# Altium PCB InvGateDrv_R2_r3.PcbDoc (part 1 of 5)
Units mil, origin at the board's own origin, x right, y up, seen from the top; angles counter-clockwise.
Board outline 6245 x 2850 mil, 4 copper layers (Top Layer, Power, Ground, Bottom Layer), stack 104.204 mil thick; 409 components, 181 nets, 1050 pads, 683 vias.
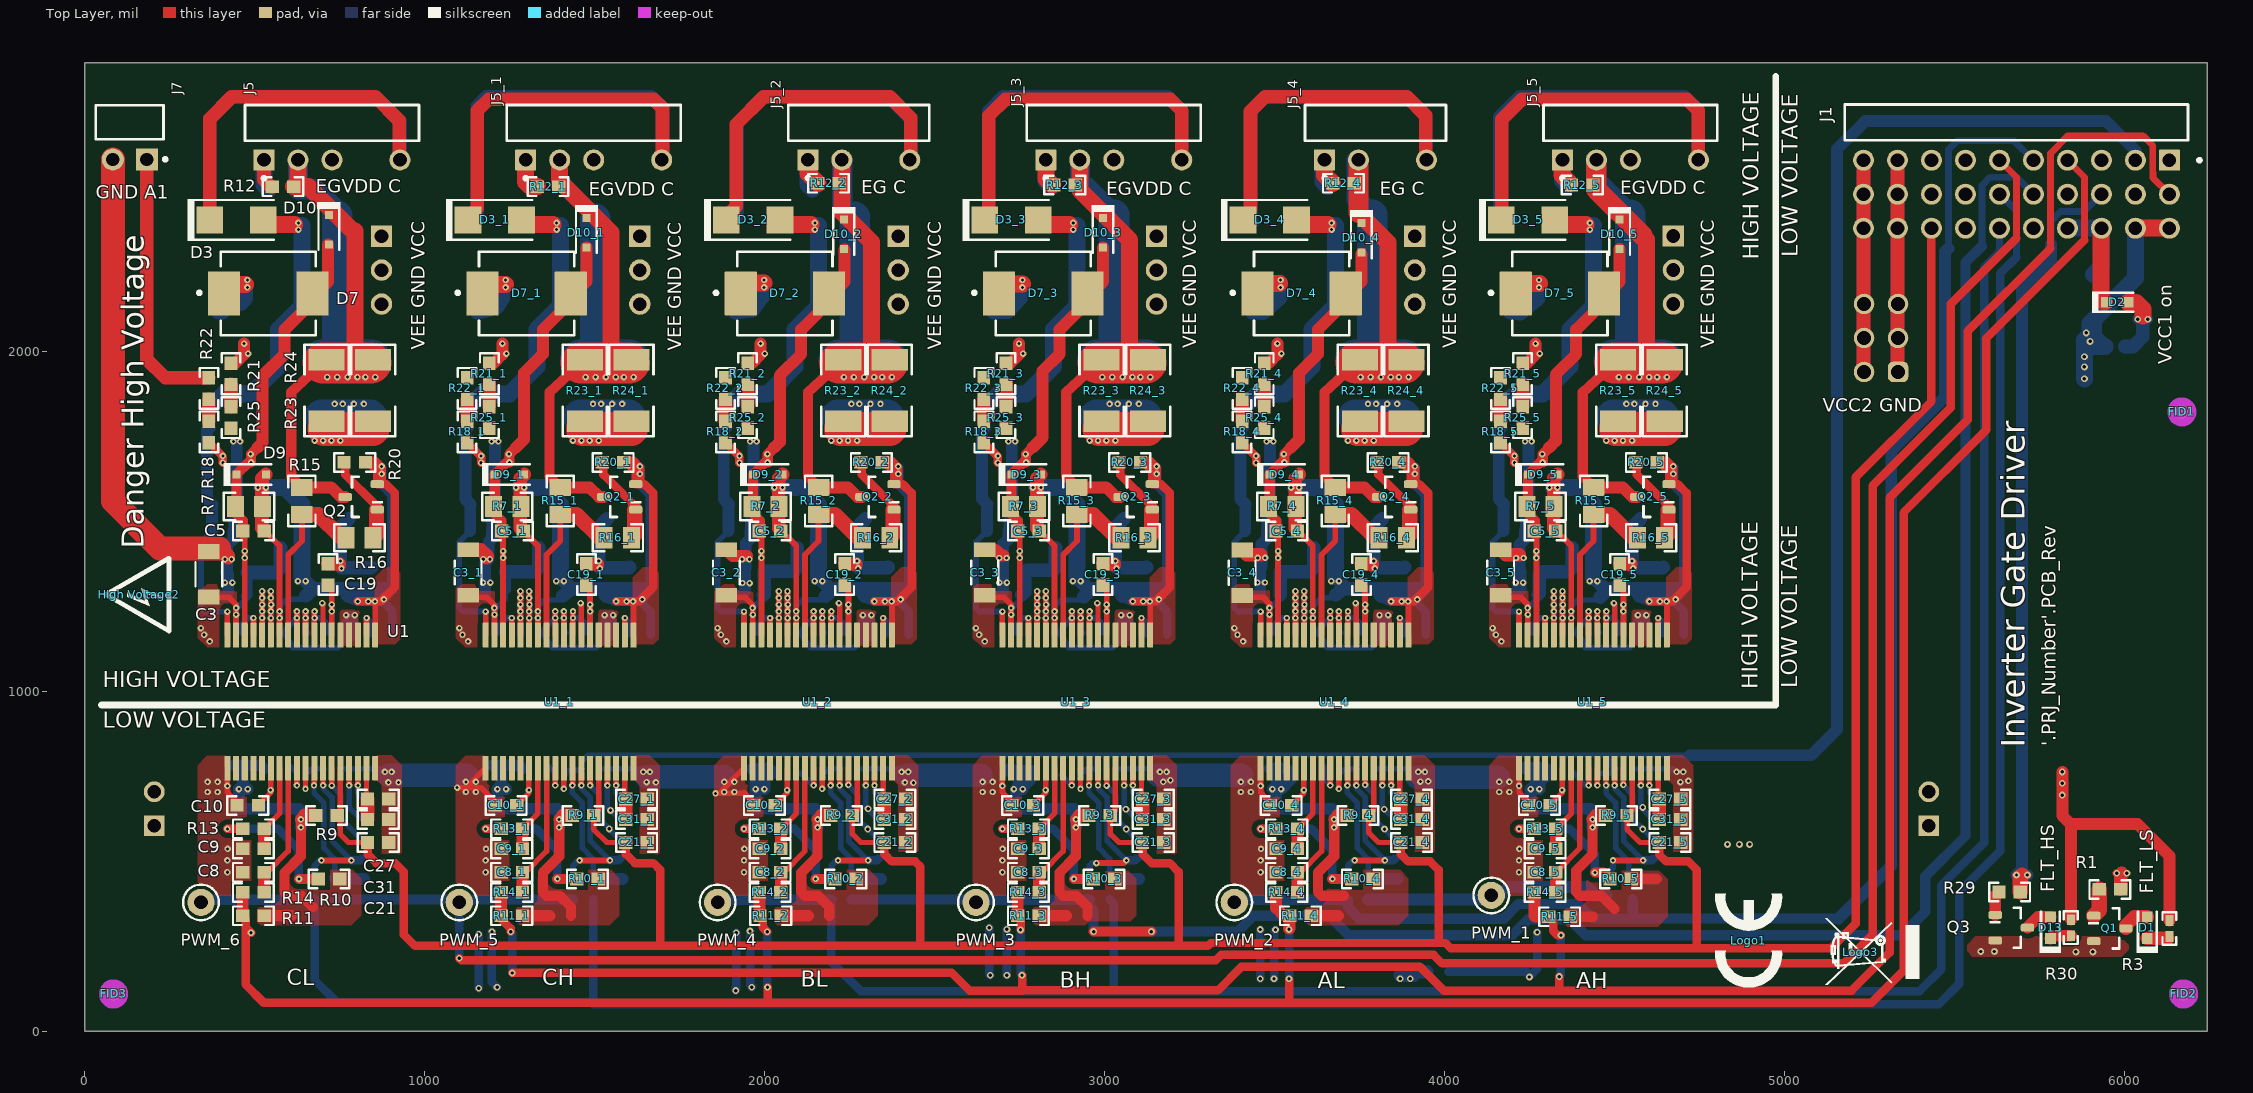
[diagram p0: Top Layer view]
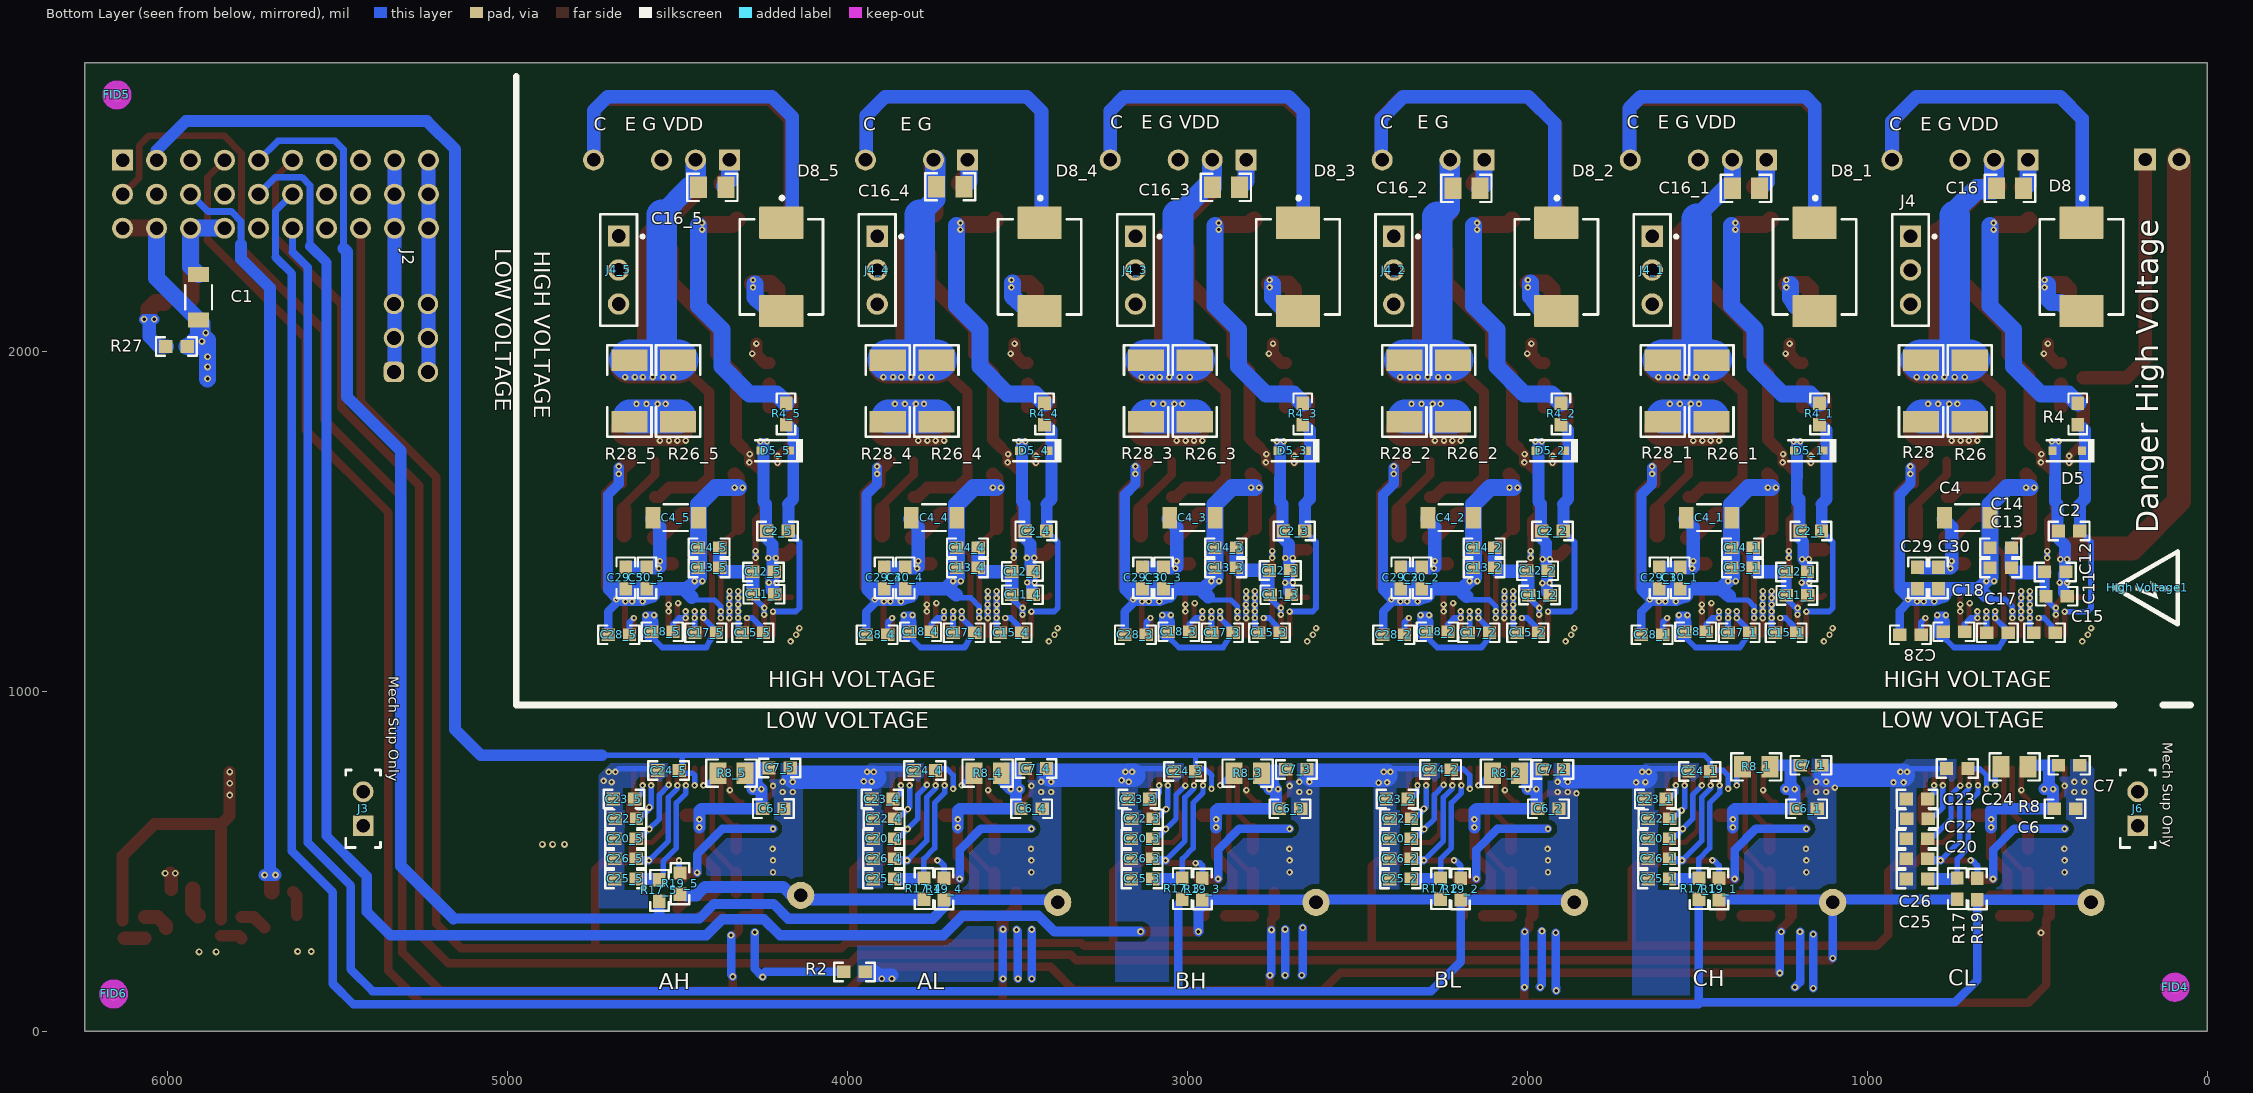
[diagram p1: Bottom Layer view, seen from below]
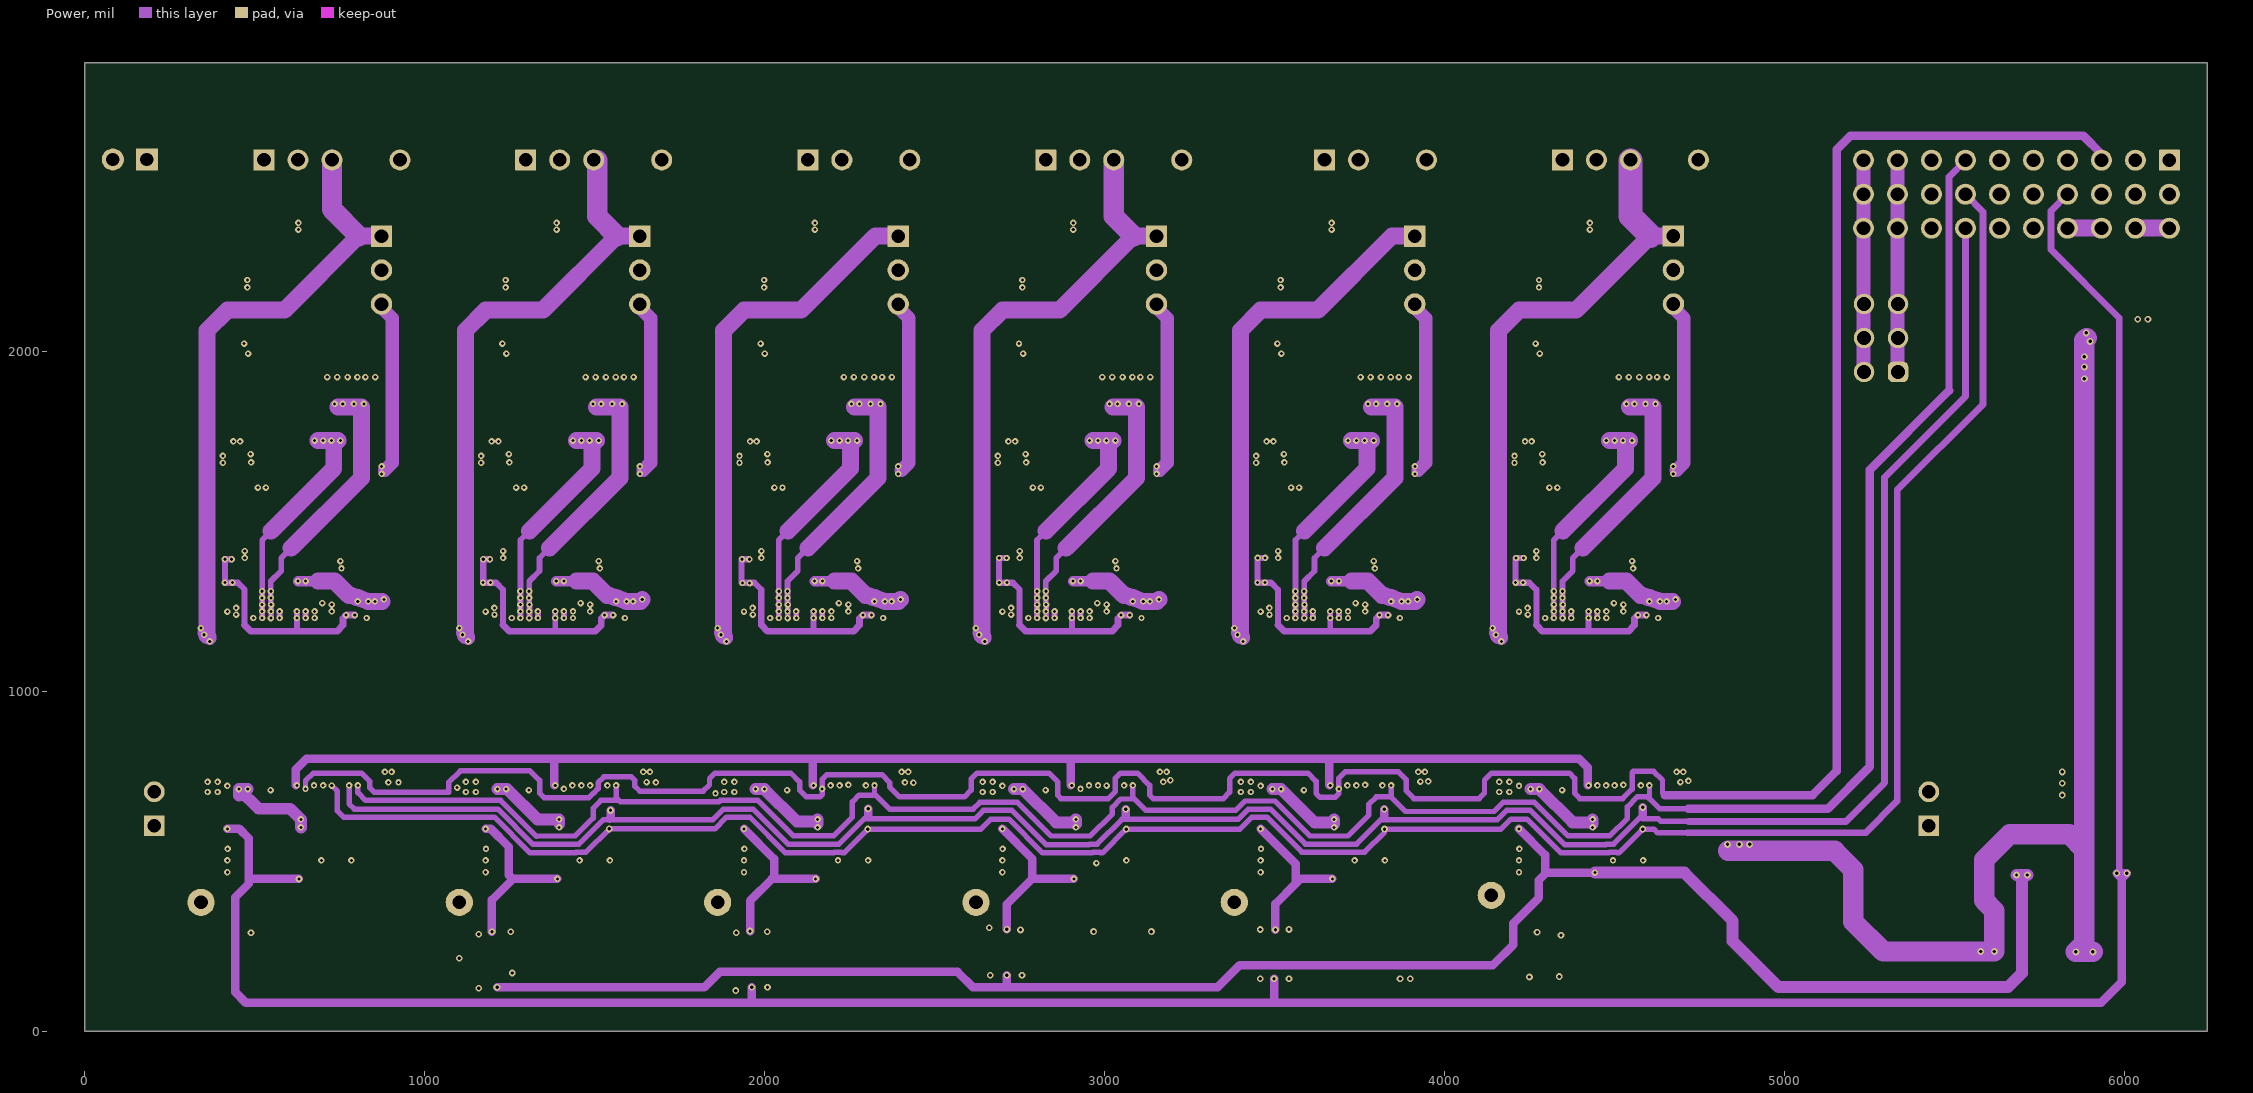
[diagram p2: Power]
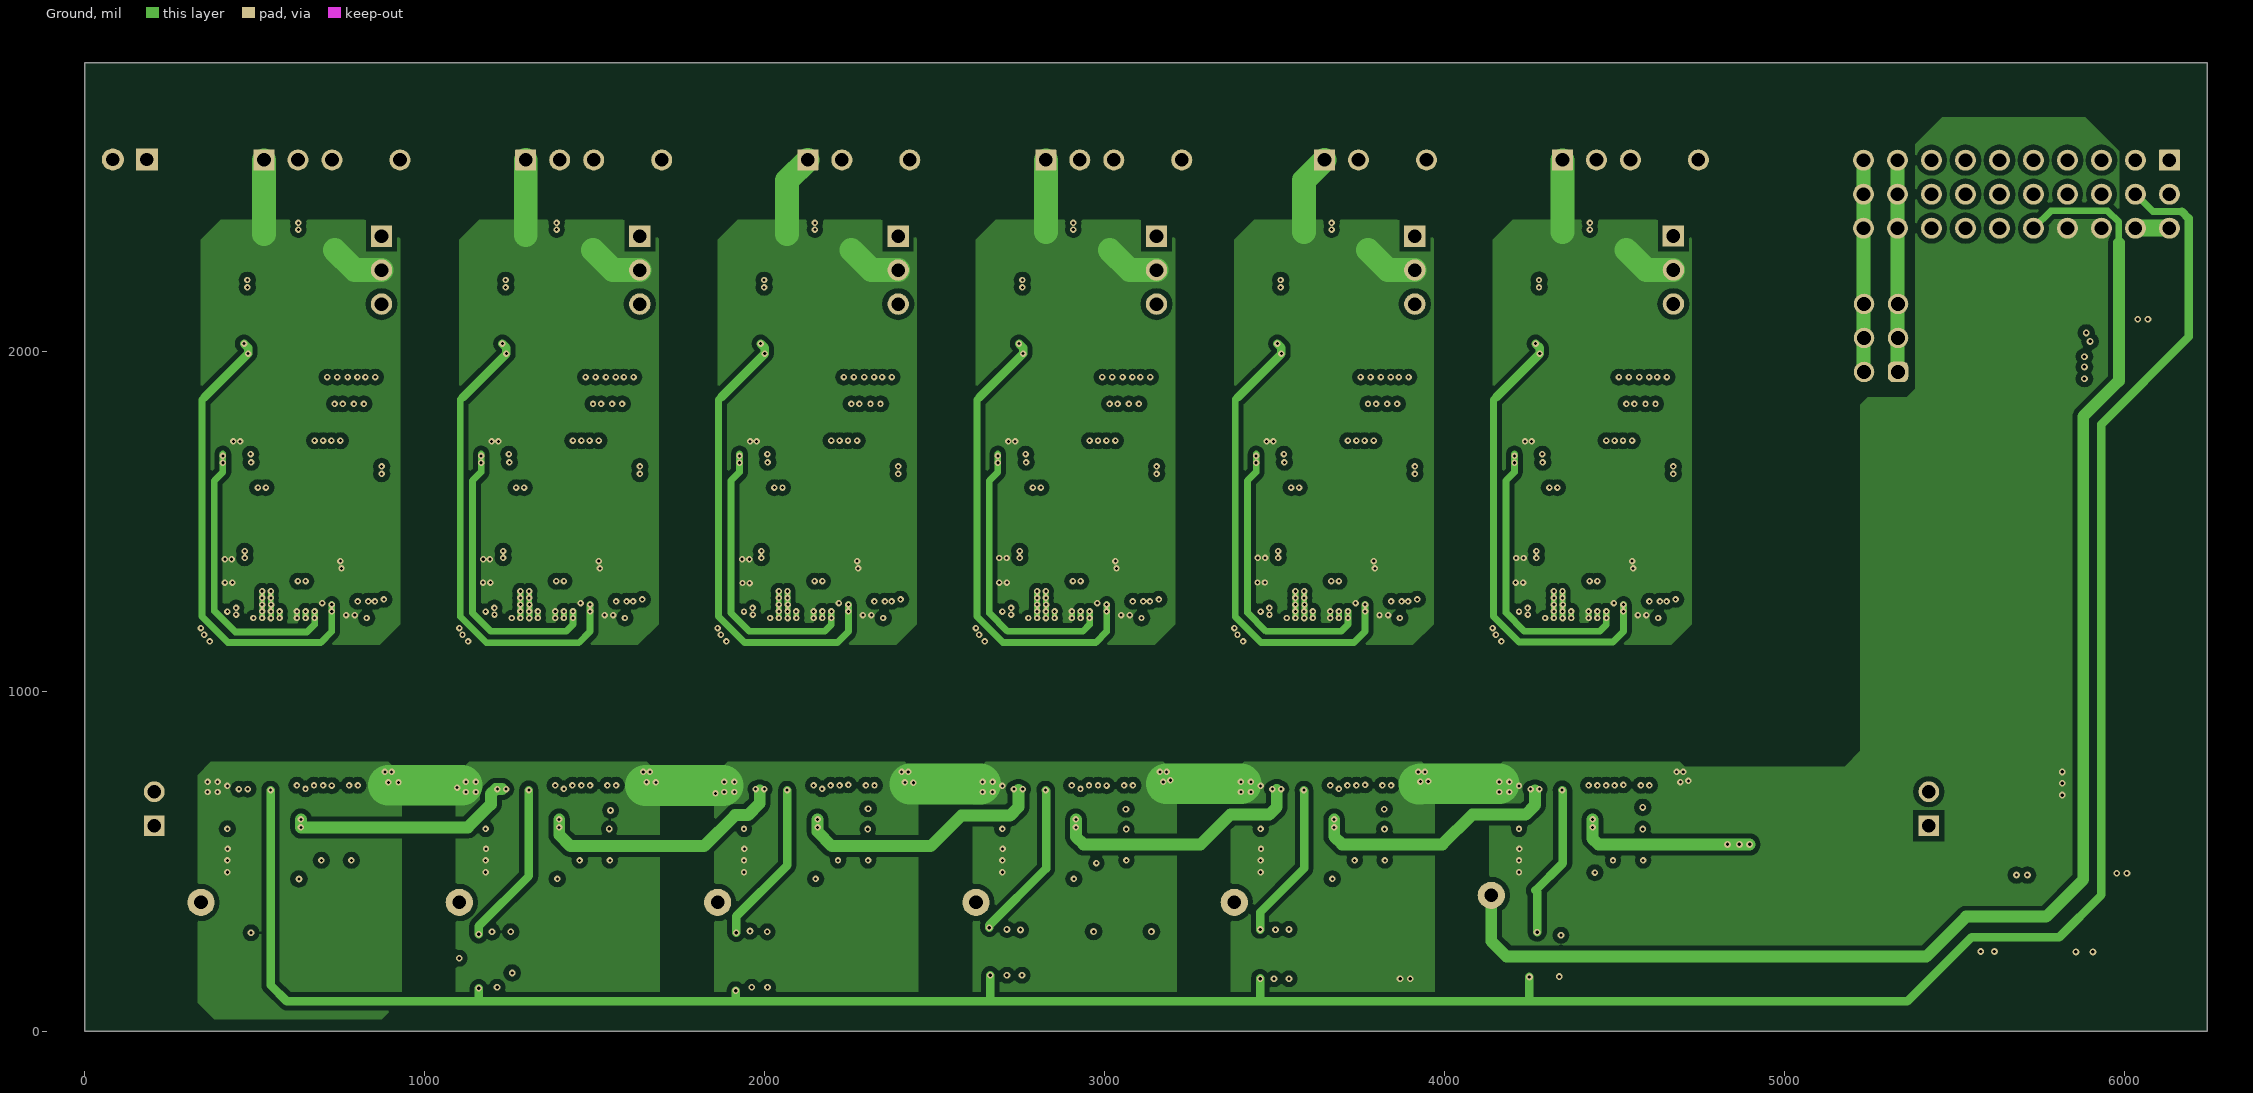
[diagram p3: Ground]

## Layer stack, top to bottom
Top Solder: solder mask 0.4, Solder Resist, Dk 3.5
Top Layer: signal copper 1.4
Dielectric 2: prepreg 19.685, FR-4, Dk 4.2
Power: signal copper 1.417
Dielectric1: core 59.2, FR-4, Dk 4.8
Ground: signal copper 1.417
Dielectric 3: prepreg 19.685, FR-4, Dk 4.2
Bottom Layer: signal copper 1.4
Bottom Solder: solder mask 0.4, Solder Resist, Dk 3.5

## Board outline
0,0 0,2850 6245,2850 6245,0

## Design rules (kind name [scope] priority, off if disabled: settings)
AcuteAngle [All] p1: minimum=4.50000000000000E+0001 checktracksonly=FALSE
AssemblyTestPointUsage [All] p1: valid=2
BoardOutlineClearance BoardOutlineClearance_MountingHoles [OnCopper and InComponentClass('Mounting Holes')] p1: gap=35 ignorepadtopadclearanceinfootprint=FALSE
BoardOutlineClearance BoardOutlineClearance_Poly [OnCopper and IsPoly] p2: gap=25 ignorepadtopadclearanceinfootprint=FALSE
BoardOutlineClearance [OnCopper and Not InComponentClass('Logo') and not InComponentClass('FiducialMark') and not InRegion(1000,500,4000,800) and not InPoly] p3: gap=25 ignorepadtopadclearanceinfootprint=FALSE
Clearance Clearance_Keepouts [((IsTrack Or IsArc) And Not InPoly) And IsFree and IsKeepOut vs ((IsTrack Or IsArc) And Not InPoly) And IsFree and IsKeepOut] p1: gap=0 ignorepadtopadclearanceinfootprint=FALSE
Clearance Clearance_Poly [InPolygon] p2: gap=15 ignorepadtopadclearanceinfootprint=TRUE
Clearance Clearance_FiducialMark [IsKeepOut and InComponentClass('FiducialMark') vs IsPad and InComponentClass('FiducialMark')] p3: gap=0 ignorepadtopadclearanceinfootprint=FALSE
Clearance [All] p4: gap=6 ignorepadtopadclearanceinfootprint=TRUE
ComponentClearance ComponentClearance_MountingHoles_FiducialMarks [InComponentClass('Mounting Holes') vs InComponentClass('FiducialMark')] p1: gap=50 collisioncheckmode=3 verticalgap=10 showdistances=FALSE
ComponentClearance ComponentClearance_Shunt [InComponentClass('Header') vs InComponentClass('Shunt')] p2: gap=0 collisioncheckmode=3 verticalgap=0 showdistances=FALSE
ComponentClearance ComponentClearance_Logo [InComponentClass('Logo')] p3: gap=50 collisioncheckmode=3 verticalgap=10 showdistances=FALSE
ComponentClearance ComponentClearance_ScrewToNut [(HasFootprint('NY PMS 440 0025 PH')) vs (HasFootprint('Keystone_1902C'))] p4: gap=5 collisioncheckmode=3 verticalgap=10 showdistances=FALSE
ComponentClearance ComponentClearance_MountingHoles [InComponentClass('Mounting Holes')] p5: gap=250 collisioncheckmode=3 verticalgap=100000 showdistances=FALSE
ComponentClearance ComponentClearance_SmallPassives [HasFootprint('0201*') or HasFootprint('0402*') or HasFootprint('0508') or HasFootprint('0603*') or HasFootprint('0612') or HasFootprint('0805*') or HasFootprint('0815*') or HasFootprint('0830*') or HasFootprint('1206*') or HasFootprint('1210*') or HasFootprint('1808*') or HasFootprint('1812*') or HasFootprint('1825*') or HasFootprint('2010*') or HasFootprint('2220*') or HasFootprint('2225*') or HasFootprint('2512*') or HasFootprint('2728*') or HasFootprint('3518*') vs HasFootprint('0201*') or HasFootprint('0402*') or HasFootprint('0508') or HasFootprint('0603*') or HasFootprint('0612') or HasFootprint('0805*') or HasFootprint('0815*') or HasFootprint('0830*') or HasFootprint('1206*') or HasFootprint('1210*') or HasFootprint('1808*') or HasFootprint('1812*') or HasFootprint('1825*') or HasFootprint('2010*') or HasFootprint('2220*') or HasFootprint('2225*') or HasFootprint('2512*') or HasFootprint('2728*') or HasFootprint('3518*')] p6: gap=14.96 collisioncheckmode=3 verticalgap=10 showdistances=FALSE
ComponentClearance ComponentClearance_THtoSMT [IsThruComponent vs IsSMTComponent] p7: gap=15 collisioncheckmode=3 verticalgap=15 showdistances=FALSE
ComponentClearance ComponentClearance_THtoTH [IsThruComponent vs IsThruComponent] p8: gap=20 collisioncheckmode=3 verticalgap=30 showdistances=FALSE
ComponentClearance [All] p9: gap=15 collisioncheckmode=3 verticalgap=10 showdistances=FALSE
DiffPairsRouting [All] p1: maxlimit=100 minlimit=10 mostfreqgap=10 toplayer_minwidth=15 toplayer_maxwidth=15 toplayer_prefwidth=15 midlayer1_minwidth=15 midlayer1_maxwidth=15 midlayer1_prefwidth=15 midlayer2_minwidth=15 midlayer2_maxwidth=15 midlayer2_prefwidth=15 bottomlayer_minwidth=15 bottomlayer_maxwidth=15 bottomlayer_prefwidth=15 maxuncoupledlength=1000
FabricationTestPointUsage TestPointUsage [All] p1: valid=2 allowmultiple=FALSE
FabricationTestpoint Testpoint [All] p1: side=3 testpointundercomponent=TRUE minsize=40 maxsize=100 preferedsize=60 minholesize=0 maxholesize=40 preferedholesize=32 testpointgrid=1 allowsidetop=TRUE allowsidebottom=TRUE usegrid=TRUE gridtolerance=0.01
FanoutControl Fanout_LCC [IsLCC] p1: bgadir=Out bgaviamode=Centered fanoutstyle=Auto fanoutdirection=Alternating viagrid=1 // Fanout_LCC (Default Rule)
FanoutControl Fanout_BGA [IsBGA] p2: bgadir=Out bgaviamode=Centered fanoutstyle=Auto fanoutdirection=Alternating viagrid=1 // Fanout_BGA (Default Rule)
FanoutControl Fanout_Default [All] p4: bgadir=Out bgaviamode=Centered fanoutstyle=Auto fanoutdirection=Alternating viagrid=1 // Fanout_Default (Default Rule)
FanoutControl Fanout_Small [(CompPinCount < 5)] p5: bgadir=Out bgaviamode=Centered fanoutstyle=Auto fanoutdirection=OutThenIn viagrid=1 // Fanout_Small (Default Rule)
HoleSize [All] p1: absolutevalues=TRUE maxlimit=251 minlimit=4 maxpercent=80.000 minpercent=20.000
MinimumAnnularRing MinimumAnnularRing_ThermalPadVias [IsVia and InAnyComponent] p1: minimumring=4
MinimumAnnularRing [All] p2: minimumring=4
MinimumSolderMaskSliver MinimumSolderMaskSliver_Logo [InComponentClass('Logo') vs InComponentClass('Logo')] p1: minsoldermaskwidth=0.7
MinimumSolderMaskSliver [All] p2: minsoldermaskwidth=1
PlaneConnect [All] p1: planeconnectstyle=Relief reliefexpansion=10 reliefentries=4 reliefconductorwidth=10 reliefairgap=10
PolygonConnect [All] p1: connectstyle=Direct reliefconductorwidth=10 reliefentries=4 polygonreliefangle="90 Angle" airgapwidth=10
RoomDefinition "Stark Gate Driver_3" [InComponentClass('Stark Gate Driver_3')] p1: confinementstyle=ConfineIn formatcopy=TRUE lockcomponents=FALSE outline 931.46,733.82 931.46,2466.1 331.46,2466.1 331.46,733.82
RoomDefinition 1 [InComponentClass('1')] p2: confinementstyle=ConfineIn formatcopy=TRUE lockcomponents=FALSE outline 4731.46,733.82 4731.46,2466.1 4131.46,2466.1 4131.46,733.82
RoomDefinition 2 [InComponentClass('2')] p3: confinementstyle=ConfineIn formatcopy=TRUE lockcomponents=FALSE outline 3971.46,733.82 3971.46,2466.1 3371.46,2466.1 3371.46,733.82
RoomDefinition 3 [InComponentClass('3')] p4: confinementstyle=ConfineIn formatcopy=TRUE lockcomponents=FALSE outline 3211.46,733.82 3211.46,2466.1 2611.46,2466.1 2611.46,733.82
RoomDefinition "Stark Gate Driver_1" [InComponentClass('Stark Gate Driver_1')] p5: confinementstyle=ConfineIn formatcopy=TRUE lockcomponents=FALSE outline 2451.46,733.82 2451.46,2466.1 1851.46,2466.1 1851.46,733.82
RoomDefinition "Stark Gate Driver_4" [InComponentClass('Stark Gate Driver_4')] p6: confinementstyle=ConfineIn formatcopy=TRUE lockcomponents=FALSE outline 1691.46,733.82 1691.46,2466.1 1091.46,2466.1 1091.46,733.82
RoutingVias ThermalPadVias [IsVia and InAnyComponent] p1: holewidth=7.87 width=19.68 viastyle="Through Hole" minholewidth=7.87 minwidth=19.68 maxholewidth=12.99 maxwidth=23.62
RoutingVias [All] p2: holewidth=16 width=34 viastyle="Through Hole" minholewidth=7.87 minwidth=15 maxholewidth=40 maxwidth=65
SilkToBoardRegionClearance [Not ((IsComment or IsDesignator) And (Hide <> 'False')) and not InRegion(1000,500,4000,800)] p1:
SilkToSilkClearance SilkToSilkClearance_Pb-FreeLogo [(HasFootprint('Pb-Free_Overlay_Medium') OR HasFootprint('Pb-Free_Overlay_Small')) vs (HasFootprint('Pb-Free_Overlay_Medium') OR HasFootprint('Pb-Free_Overlay_Small'))] p1: silktosilkclearance=0
SilkToSilkClearance [All] p2: silktosilkclearance=0
SilkToSolderMaskClearance SilkToComponentPadClearance [(IsPad or IsFill or IsRegion) and InAnycomponent] p1: minsilkscreentomaskgap=0 clearancetoexposedcopper=TRUE
SilkToSolderMaskClearance "Silk to Solder Mask Opening" [All] p2: minsilkscreentomaskgap=0 clearancetoexposedcopper=FALSE
SolderMaskExpansion [All] p1: expansion=1.97
UnRoutedNet [All] p1: checkbadconnections=TRUE
Width [All] p1: maxlimit=180 minlimit=6 preferedwidth=10 checkconnectedcopper=TRUE
14 further rules are at their usual default settings.

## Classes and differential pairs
component class "Hardware and Connector_r1": !PCB1 C1 D1 D2 D13 FID1 FID2 FID3 FID4 FID5 FID6 "High Voltage1" "High Voltage2" J1 J2 J3 J6 Logo1 Logo3 Q1 Q3 R1 R2 R3 R27 R29 R30 ZZ1 ZZ2 ZZ3 ZZ4
component class FiducialMark: FID1 FID2 FID3 FID4 FID5 FID6
component class AssemblyNote: ZZ1 ZZ2 ZZ3 ZZ4
component class "Stark Gate Driver_6": C2_5 C3_5 C4_5 C5_5 C6_5 C7_5 C8_5 C9_5 C10_5 C11_5 C12_5 C13_5 C14_5 C15_5 C16_5 C17_5 C18_5 C19_5 C20_5 C21_5 C22_5 C23_5 C24_5 C25_5 C26_5 C27_5 C28_5 C29_5 C30_5 C31_5 D3_5 D5_5 D7_5 D8_5 D9_5 D10_5 J4_5 J5_5 PWM_ PWM_1 Q2_5 R4_5 R7_5 R8_5 R9_5 R10_5 R11_5 R12_5 R13_5 R14_5 R15_5 R16_5 R17_5 R18_5 R19_5 R20_5 R21_5 R22_5 R23_5 R24_5 R25_5 R26_5 R28_5 U1_5
component class "Stark Gate Driver_5": C2_4 C3_4 C4_4 C5_4 C6_4 C7_4 C8_4 C9_4 C10_4 C11_4 C12_4 C13_4 C14_4 C15_4 C16_4 C17_4 C18_4 C19_4 C20_4 C21_4 C22_4 C23_4 C24_4 C25_4 C26_4 C27_4 C28_4 C29_4 C30_4 C31_4 D3_4 D5_4 D7_4 D8_4 D9_4 D10_4 J4_4 J5_4 PWM_2 Q2_4 R4_4 R7_4 R8_4 R9_4 R10_4 R11_4 R12_4 R13_4 R14_4 R15_4 R16_4 R17_4 R18_4 R19_4 R20_4 R21_4 R22_4 R23_4 R24_4 R25_4 R26_4 R28_4 U1_4
component class "Stark Gate Driver_4": C2_3 C3_3 C4_3 C5_3 C6_3 C7_3 C8_3 C9_3 C10_3 C11_3 C12_3 C13_3 C14_3 C15_3 C16_3 C17_3 C18_3 C19_3 C20_3 C21_3 C22_3 C23_3 C24_3 C25_3 C26_3 C27_3 C28_3 C29_3 C30_3 C31_3 D3_3 D5_3 D7_3 D8_3 D9_3 D10_3 J4_3 J5_3 PWM_3 Q2_3 R4_3 R7_3 R8_3 R9_3 R10_3 R11_3 R12_3 R13_3 R14_3 R15_3 R16_3 R17_3 R18_3 R19_3 R20_3 R21_3 R22_3 R23_3 R24_3 R25_3 R26_3 R28_3 U1_3
component class "Stark Gate Driver_3": C2_2 C3_2 C4_2 C5_2 C6_2 C7_2 C8_2 C9_2 C10_2 C11_2 C12_2 C13_2 C14_2 C15_2 C16_2 C17_2 C18_2 C19_2 C20_2 C21_2 C22_2 C23_2 C24_2 C25_2 C26_2 C27_2 C28_2 C29_2 C30_2 C31_2 D3_2 D5_2 D7_2 D8_2 D9_2 D10_2 J4_2 J5_2 PWM_4 Q2_2 R4_2 R7_2 R8_2 R9_2 R10_2 R11_2 R12_2 R13_2 R14_2 R15_2 R16_2 R17_2 R18_2 R19_2 R20_2 R21_2 R22_2 R23_2 R24_2 R25_2 R26_2 R28_2 U1_2
component class "Stark Gate Driver_2": C2_1 C3_1 C4_1 C5_1 C6_1 C7_1 C8_1 C9_1 C10_1 C11_1 C12_1 C13_1 C14_1 C15_1 C16_1 C17_1 C18_1 C19_1 C20_1 C21_1 C22_1 C23_1 C24_1 C25_1 C26_1 C27_1 C28_1 C29_1 C30_1 C31_1 D3_1 D5_1 D7_1 D8_1 D9_1 D10_1 J4_1 J5_1 PWM_5 Q2_1 R4_1 R7_1 R8_1 R9_1 R10_1 R11_1 R12_1 R13_1 R14_1 R15_1 R16_1 R17_1 R18_1 R19_1 R20_1 R21_1 R22_1 R23_1 R24_1 R25_1 R26_1 R28_1 U1_1
component class "Stark Gate Driver_1": C2 C3 C4 C5 C6 C7 C8 C9 C10 C11 C12 C13 C14 C15 C16 C17 C18 C19 C20 C21 C22 C23 C24 C25 C26 C27 C28 C29 C30 C31 D3 D5 D7 D8 D9 D10 J4 J5 J7 PWM_ PWM_6 Q2 R4 R7 R8 R9 R10 R11 R12 R13 R14 R15 R16 R17 R18 R19 R20 R21 R22 R23 R24 R25 R26 R28 U1

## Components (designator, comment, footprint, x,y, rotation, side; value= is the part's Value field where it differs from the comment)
C1 "C3216X5R1H106K160AB" 1206_180 5910,2160 r90 bottom value=10uF
C2 "GRM188R71H221KA01D" 0603 406.57,1472.01 r180 bottom value=220pF
C2_1 "GRM188R71H221KA01D" 0603 1166.57,1472.01 r180 bottom value=220pF
C2_2 "GRM188R71H221KA01D" 0603 1926.57,1472.01 r180 bottom value=220pF
C2_3 "GRM188R71H221KA01D" 0603 2686.57,1472.01 r180 bottom value=220pF
C2_4 "GRM188R71H221KA01D" 0603 3446.57,1472.01 r180 bottom value=220pF
C2_5 "GRM188R71H221KA01D" 0603 4206.57,1472.01 r180 bottom value=220pF
C3 "CL31B106KBHNNNE" 1206_180 365.39,1345 r270 top value=10uF
C3_1 "CL31B106KBHNNNE" 1206_180 1128.08,1350 r270 top value=10uF
C3_2 "CL31B106KBHNNNE" 1206_180 1887.87,1350 r270 top value=10uF
C3_3 "CL31B106KBHNNNE" 1206_180 2648.08,1350 r270 top value=10uF
C3_4 "CL31B106KBHNNNE" 1206_180 3405.39,1349.49 r270 top value=10uF
C3_5 "CL31B106KBHNNNE" 1206_180 4166.08,1350 r270 top value=10uF
C4 "CL31B106KBHNNNE" 1206_180 706.1,1511.38 r180 bottom value=10uF
C4_1 "CL31B106KBHNNNE" 1206_180 1466.1,1511.38 r180 bottom value=10uF
C4_2 "CL31B106KBHNNNE" 1206_180 2226.1,1511.38 r180 bottom value=10uF
C4_3 "CL31B106KBHNNNE" 1206_180 2986.1,1511.38 r180 bottom value=10uF
C4_4 "CL31B106KBHNNNE" 1206_180 3746.1,1511.38 r180 bottom value=10uF
C4_5 "CL31B106KBHNNNE" 1206_180 4506.1,1511.38 r180 bottom value=10uF
C5 "GRM188R71H103KA01D" 0603 496.61,1472.01 r0 top value=0.01uF
C5_1 "GRM188R71H103KA01D" 0603 1258.35,1472.01 r0 top value=0.01uF
C5_2 "GRM188R71H103KA01D" 0603 2016.61,1472.01 r0 top value=0.01uF
C5_3 "GRM188R71H103KA01D" 0603 2776.61,1472.01 r0 top value=0.01uF
C5_4 "GRM188R71H103KA01D" 0603 3536.61,1472.01 r0 top value=0.01uF
C5_5 "GRM188R71H103KA01D" 0603 4296.61,1472.01 r0 top value=0.01uF
C6 "GCM188R71C105MA64D" 0603 418.86,655.08 r180 bottom value=1uF
C6_1 "GCM188R71C105MA64D" 0603 1178.85,655.08 r180 bottom value=1uF
C6_2 "GCM188R71C105MA64D" 0603 1938.86,655.08 r180 bottom value=1uF
C6_3 "GCM188R71C105MA64D" 0603 2698.86,655.08 r180 bottom value=1uF
C6_4 "GCM188R71C105MA64D" 0603 3458.86,655.08 r180 bottom value=1uF
C6_5 "GCM188R71C105MA64D" 0603 4218.86,655.08 r180 bottom value=1uF
C7 "CGJ3E2X7R1C104K080AA" 0603 406.46,783.03 r180 bottom value=0.1uF
C7_1 "CGJ3E2X7R1C104K080AA" 0603 1166.45,783.03 r180 bottom value=0.1uF
C7_2 "CGJ3E2X7R1C104K080AA" 0603 1925.67,770.91 r180 bottom value=0.1uF
C7_3 "CGJ3E2X7R1C104K080AA" 0603 2680.23,770.91 r180 bottom value=0.1uF
C7_4 "CGJ3E2X7R1C104K080AA" 0603 3446.57,773.19 r180 bottom value=0.1uF
C7_5 "CGJ3E2X7R1C104K080AA" 0603 4200.23,775 r180 bottom value=0.1uF
C8 "GCM1885C1H101JA16J" 0603 496.61,468.07 r0 top value=100pF
C8_1 "GCM1885C1H101JA16J" 0603 1256.61,468.07 r0 top value=100pF
C8_2 "GCM1885C1H101JA16J" 0603 2016.61,468.07 r0 top value=100pF
C8_3 "GCM1885C1H101JA16J" 0603 2776.61,468.07 r0 top value=100pF
C8_4 "GCM1885C1H101JA16J" 0603 3536.61,468.07 r0 top value=100pF
C8_5 "GCM1885C1H101JA16J" 0603 4296.61,468.08 r0 top value=100pF
C9 "GCM1885C1H101JA16J" 0603 496.61,536.97 r0 top value=100pF
C9_1 "GCM1885C1H101JA16J" 0603 1256.61,536.97 r0 top value=100pF
C9_2 "GCM1885C1H101JA16J" 0603 2016.61,536.97 r0 top value=100pF
C9_3 "GCM1885C1H101JA16J" 0603 2776.61,536.97 r0 top value=100pF
C9_4 "GCM1885C1H101JA16J" 0603 3536.61,536.97 r0 top value=100pF
C9_5 "GCM1885C1H101JA16J" 0603 4296.61,536.97 r0 top value=100pF
C10 "GCM1885C1H101JA16J" 0603 479.88,664.92 r0 top value=100pF
C10_1 "GCM1885C1H101JA16J" 0603 1239.88,664.92 r0 top value=100pF
C10_2 "GCM1885C1H101JA16J" 0603 1999.88,664.92 r0 top value=100pF
C10_3 "GCM1885C1H101JA16J" 0603 2759.88,664.92 r0 top value=100pF
C10_4 "GCM1885C1H101JA16J" 0603 3519.88,664.92 r0 top value=100pF
C10_5 "GCM1885C1H101JA16J" 0603 4279.88,664.93 r0 top value=100pF
C11 "C1608X5R1H104K080AA" 0603 443.27,1280 r180 bottom value=0.1uF
C11_1 "C1608X5R1H104K080AA" 0603 1207.49,1282.88 r180 bottom value=0.1uF
C11_2 "C1608X5R1H104K080AA" 0603 1964.84,1283.47 r180 bottom value=0.1uF
C11_3 "C1608X5R1H104K080AA" 0603 2725.83,1284.45 r180 bottom value=0.1uF
C11_4 "C1608X5R1H104K080AA" 0603 3485.83,1284.45 r180 bottom value=0.1uF
C11_5 "C1608X5R1H104K080AA" 0603 4246.63,1285.99 r180 bottom value=0.1uF
C12 "CGA3E1X7R1V105K080AC" 0603 447.49,1351.93 r180 bottom value=1uF
C12_1 "CGA3E1X7R1V105K080AC" 0603 1207.86,1351.93 r180 bottom value=1uF
C12_2 "CGA3E1X7R1V105K080AC" 0603 1970.35,1355 r180 bottom value=1uF
C12_3 "CGA3E1X7R1V105K080AC" 0603 2727.76,1355.63 r180 bottom value=1uF
C12_4 "CGA3E1X7R1V105K080AC" 0603 3486.18,1352.8 r180 bottom value=1uF
C12_5 "CGA3E1X7R1V105K080AC" 0603 4247.86,1351.93 r180 bottom value=1uF
C13 "C1608X5R1H104K080AA" 0603 607.83,1363.74 r0 bottom value=0.1uF
C13_1 "C1608X5R1H104K080AA" 0603 1367.83,1363.74 r0 bottom value=0.1uF
C13_2 "C1608X5R1H104K080AA" 0603 2127.83,1363.74 r0 bottom value=0.1uF
C13_3 "C1608X5R1H104K080AA" 0603 2887.83,1363.74 r0 bottom value=0.1uF
C13_4 "C1608X5R1H104K080AA" 0603 3647.83,1363.74 r0 bottom value=0.1uF
C13_5 "C1608X5R1H104K080AA" 0603 4407.83,1363.74 r0 bottom value=0.1uF
C14 "CGA3E1X7R1V105K080AC" 0603 607.83,1422.8 r0 bottom value=1uF
C14_1 "CGA3E1X7R1V105K080AC" 0603 1367.83,1422.8 r0 bottom value=1uF
C14_2 "CGA3E1X7R1V105K080AC" 0603 2127.83,1422.79 r0 bottom value=1uF
C14_3 "CGA3E1X7R1V105K080AC" 0603 2887.83,1422.8 r0 bottom value=1uF
C14_4 "CGA3E1X7R1V105K080AC" 0603 3647.83,1422.79 r0 bottom value=1uF
C14_5 "CGA3E1X7R1V105K080AC" 0603 4407.83,1422.8 r0 bottom value=1uF
C15 "C1608X5R1H104K080AA" 0603 479.25,1172.8 r0 bottom value=0.1uF
C15_1 "C1608X5R1H104K080AA" 0603 1239.25,1172.8 r0 bottom value=0.1uF
C15_2 "C1608X5R1H104K080AA" 0603 1999.25,1172.79 r0 bottom value=0.1uF
C15_3 "C1608X5R1H104K080AA" 0603 2759.25,1172.8 r0 bottom value=0.1uF
C15_4 "C1608X5R1H104K080AA" 0603 3519.25,1172.79 r0 bottom value=0.1uF
C15_5 "C1608X5R1H104K080AA" 0603 4279.25,1172.8 r0 bottom value=0.1uF
C16 "C0805C104K5RACAUTO" 0805_HV 580.54,2480 r180 bottom value=0.1uF
C16_1 "C0805C104K5RACAUTO" 0805_HV 1357.52,2480 r180 bottom value=0.1uF
C16_2 "C0805C104K5RACAUTO" 0805_HV 2180,2480 r180 bottom value=0.1uF
C16_3 "C0805C104K5RACAUTO" 0805_HV 2887.52,2482.99 r180 bottom value=0.1uF
C16_4 "C0805C104K5RACAUTO" 0805_HV 3698.35,2485 r180 bottom value=0.1uF
C16_5 "C0805C104K5RACAUTO" 0805_HV 4398.35,2483 r180 bottom value=0.1uF
C17 "CGA3E1X7R1V105K080AC" 0603 617.68,1172.8 r180 bottom value=1uF
C17_1 "CGA3E1X7R1V105K080AC" 0603 1377.67,1172.8 r180 bottom value=1uF
C17_2 "CGA3E1X7R1V105K080AC" 0603 2143.35,1172.79 r180 bottom value=1uF
C17_3 "CGA3E1X7R1V105K080AC" 0603 2897.68,1172.8 r180 bottom value=1uF
C17_4 "CGA3E1X7R1V105K080AC" 0603 3657.68,1172.79 r180 bottom value=1uF
C17_5 "CGA3E1X7R1V105K080AC" 0603 4417.67,1172.8 r180 bottom value=1uF
C18 "GCM1885C1H101JA16J" 0603 745.63,1175.86 r0 bottom value=100pF
C18_1 "GCM1885C1H101JA16J" 0603 1505.63,1175.87 r0 bottom value=100pF
C18_2 "GCM1885C1H101JA16J" 0603 2265.63,1175.86 r0 bottom value=100pF
C18_3 "GCM1885C1H101JA16J" 0603 3025.63,1175.86 r0 bottom value=100pF
C18_4 "GCM1885C1H101JA16J" 0603 3785.63,1175.86 r0 bottom value=100pF
C18_5 "GCM1885C1H101JA16J" 0603 4545.63,1175.87 r0 bottom value=100pF
C19 "GCM1885C1H101JA16J" 0603 716.1,1344.06 r90 top value=100pF
C19_1 "GCM1885C1H101JA16J" 0603 1476.1,1344.06 r90 top value=100pF
C19_2 "GCM1885C1H101JA16J" 0603 2236.1,1344.05 r90 top value=100pF
C19_3 "GCM1885C1H101JA16J" 0603 2996.1,1344.06 r90 top value=100pF
C19_4 "GCM1885C1H101JA16J" 0603 3756.1,1344.05 r90 top value=100pF
C19_5 "GCM1885C1H101JA16J" 0603 4516.1,1344.06 r90 top value=100pF
C20 "GCM1885C1H101JA16J" 0603 853.9,566.5 r0 bottom value=100pF
C20_1 "GCM1885C1H101JA16J" 0603 1613.89,566.5 r0 bottom value=100pF
C20_2 "GCM1885C1H101JA16J" 0603 2373.9,566.5 r0 bottom value=100pF
C20_3 "GCM1885C1H101JA16J" 0603 3133.9,566.5 r0 bottom value=100pF
C20_4 "GCM1885C1H101JA16J" 0603 3893.9,566.5 r0 bottom value=100pF
C20_5 "GCM1885C1H101JA16J" 0603 4653.89,566.5 r0 bottom value=100pF
C21 "GCM1885C1H101JA16J" 0603 863.74,555.67 r0 top value=100pF
C21_1 "GCM1885C1H101JA16J" 0603 1623.74,555.67 r0 top value=100pF
C21_2 "GCM1885C1H101JA16J" 0603 2383.74,555.67 r0 top value=100pF
C21_3 "GCM1885C1H101JA16J" 0603 3143.74,555.67 r0 top value=100pF
C21_4 "GCM1885C1H101JA16J" 0603 3903.74,555.67 r0 top value=100pF
C21_5 "GCM1885C1H101JA16J" 0603 4663.74,555.67 r0 top value=100pF
C22 "GCM1885C1H101JA16J" 0603 852.91,625.55 r0 bottom value=100pF
C22_1 "GCM1885C1H101JA16J" 0603 1612.91,625.55 r0 bottom value=100pF
C22_2 "GCM1885C1H101JA16J" 0603 2372.91,625.55 r0 bottom value=100pF
C22_3 "GCM1885C1H101JA16J" 0603 3132.91,625.55 r0 bottom value=100pF
C22_4 "GCM1885C1H101JA16J" 0603 3892.91,625.55 r0 bottom value=100pF
C22_5 "GCM1885C1H101JA16J" 0603 4652.91,625.56 r0 bottom value=100pF
C23 "GCM1885C1H101JA16J" 0603 853.9,683.62 r0 bottom value=100pF
C23_1 "GCM1885C1H101JA16J" 0603 1623.74,683.62 r0 bottom value=100pF
C23_2 "GCM1885C1H101JA16J" 0603 2383.35,683.62 r0 bottom value=100pF
C23_3 "GCM1885C1H101JA16J" 0603 3143.35,683.62 r0 bottom value=100pF
C23_4 "GCM1885C1H101JA16J" 0603 3898.35,683.62 r0 bottom value=100pF
C23_5 "GCM1885C1H101JA16J" 0603 4658.35,683.63 r0 bottom value=100pF
C24 "GCM1885C1H101JA16J" 0603 735.79,773.19 r0 bottom value=100pF
C24_1 "GCM1885C1H101JA16J" 0603 1493.35,765 r0 bottom value=100pF
C24_2 "GCM1885C1H101JA16J" 0603 2255.63,770 r0 bottom value=100pF
C24_3 "GCM1885C1H101JA16J" 0603 3008.35,765 r0 bottom value=100pF
C24_4 "GCM1885C1H101JA16J" 0603 3773.35,767.28 r0 bottom value=100pF
C24_5 "GCM1885C1H101JA16J" 0603 4526.93,767.29 r0 bottom value=100pF
C25 "GCM1885C1H101JA16J" 0603 853.9,448.39 r0 bottom value=100pF
C25_1 "GCM1885C1H101JA16J" 0603 1613.89,448.39 r0 bottom value=100pF
C25_2 "GCM1885C1H101JA16J" 0603 2373.9,448.39 r0 bottom value=100pF
C25_3 "GCM1885C1H101JA16J" 0603 3133.9,448.39 r0 bottom value=100pF
C25_4 "GCM1885C1H101JA16J" 0603 3893.9,448.39 r0 bottom value=100pF
C25_5 "GCM1885C1H101JA16J" 0603 4653.89,448.39 r0 bottom value=100pF
C26 "GCM1885C1H101JA16J" 0603 853.9,507.44 r0 bottom value=100pF
C26_1 "GCM1885C1H101JA16J" 0603 1613.89,507.44 r0 bottom value=100pF
C26_2 "GCM1885C1H101JA16J" 0603 2373.9,507.44 r0 bottom value=100pF
C26_3 "GCM1885C1H101JA16J" 0603 3133.9,507.44 r0 bottom value=100pF
C26_4 "GCM1885C1H101JA16J" 0603 3893.9,507.44 r0 bottom value=100pF
C26_5 "GCM1885C1H101JA16J" 0603 4653.89,507.45 r0 bottom value=100pF
C27 "CL10B475KQ8NQND" 0603 863.74,683.62 r0 top value=4.7uF
C27_1 "CL10B475KQ8NQND" 0603 1623.74,683.62 r0 top value=4.7uF
C27_2 "CL10B475KQ8NQND" 0603 2383.74,683.62 r0 top value=4.7uF
C27_3 "CL10B475KQ8NQND" 0603 3143.74,683.62 r0 top value=4.7uF
C27_4 "CL10B475KQ8NQND" 0603 3903.74,683.62 r0 top value=4.7uF
C27_5 "CL10B475KQ8NQND" 0603 4663.74,683.63 r0 top value=4.7uF
C28 "CL10B475KQ8NQND" 0603 873.58,1166.89 r0 bottom value=4.7uF
C28_1 "CL10B475KQ8NQND" 0603 1633.58,1166.89 r0 bottom value=4.7uF
C28_2 "CL10B475KQ8NQND" 0603 2393.58,1166.89 r0 bottom value=4.7uF
C28_3 "CL10B475KQ8NQND" 0603 3153.58,1166.89 r0 bottom value=4.7uF
C28_4 "CL10B475KQ8NQND" 0603 3913.58,1166.89 r0 bottom value=4.7uF
C28_5 "CL10B475KQ8NQND" 0603 4673.58,1166.89 r0 bottom value=4.7uF
C29 "C1608X5R1H104K080AA" 0603 852.91,1334.21 r90 bottom value=0.1uF
C29_1 "C1608X5R1H104K080AA" 0603 1612.91,1334.21 r90 bottom value=0.1uF
C29_2 "C1608X5R1H104K080AA" 0603 2372.91,1334.21 r90 bottom value=0.1uF
C29_3 "C1608X5R1H104K080AA" 0603 3132.91,1334.21 r90 bottom value=0.1uF
C29_4 "C1608X5R1H104K080AA" 0603 3892.91,1334.21 r90 bottom value=0.1uF
C29_5 "C1608X5R1H104K080AA" 0603 4652.91,1334.22 r90 bottom value=0.1uF
C30 "CGA3E1X7R1V105K080AC" 0603 790.92,1334.21 r270 bottom value=1uF
C30_1 "CGA3E1X7R1V105K080AC" 0603 1550.92,1334.21 r270 bottom value=1uF
C30_2 "CGA3E1X7R1V105K080AC" 0603 2310.92,1334.21 r270 bottom value=1uF
C30_3 "CGA3E1X7R1V105K080AC" 0603 3070.92,1334.21 r270 bottom value=1uF
C30_4 "CGA3E1X7R1V105K080AC" 0603 3830.92,1334.21 r270 bottom value=1uF
C30_5 "CGA3E1X7R1V105K080AC" 0603 4590.92,1334.22 r270 bottom value=1uF
C31 "CGJ3E2X7R1C104K080AA" 0603 863.74,623.58 r0 top value=0.1uF
C31_1 "CGJ3E2X7R1C104K080AA" 0603 1623.74,623.58 r0 top value=0.1uF
C31_2 "CGJ3E2X7R1C104K080AA" 0603 2383.74,623.58 r0 top value=0.1uF
C31_3 "CGJ3E2X7R1C104K080AA" 0603 3143.74,623.58 r0 top value=0.1uF
C31_4 "CGJ3E2X7R1C104K080AA" 0603 3903.74,623.58 r0 top value=0.1uF
C31_5 "CGJ3E2X7R1C104K080AA" 0603 4663.74,623.59 r0 top value=0.1uF
D1 "150060RS75000" WL-SMCW_RED 6068.35,305 r90 top value=Red
D2 "150060GS75000" WL-SMCW_GREEN 5980,2145 r0 top value=Green
D3 "STTH112A" SMA 446.61,2387.36 r0 top value=1200V
D3_1 "STTH112A" SMA 1206.61,2387.36 r0 top value=1200V
D3_2 "STTH112A" SMA 1966.61,2387.36 r0 top value=1200V
D3_3 "STTH112A" SMA 2726.61,2387.36 r0 top value=1200V
D3_4 "STTH112A" SMA 3486.61,2387.36 r0 top value=1200V
D3_5 "STTH112A" SMA 4246.61,2387.37 r0 top value=1200V
D5 "BAT54WS-7-F" SOD-323 412.67,1708.23 r0 bottom value=30V
D5_1 "BAT54WS-7-F" SOD-323 1172.66,1708.23 r0 bottom value=30V
D5_2 "BAT54WS-7-F" SOD-323 1932.67,1708.23 r0 bottom value=30V
D5_3 "BAT54WS-7-F" SOD-323 2692.67,1708.23 r0 bottom value=30V
D5_4 "BAT54WS-7-F" SOD-323 3452.67,1708.23 r0 bottom value=30V
D5_5 "BAT54WS-7-F" SOD-323 4212.66,1708.23 r0 bottom value=30V
D7 "SMCJ300A" FP-SMCJ300A_DO214AB-MFG 540.2,2170.83 r0 top
D7_1 "SMCJ300A" FP-SMCJ300A_DO214AB-MFG 1300.19,2170.83 r0 top
D7_2 "SMCJ300A" FP-SMCJ300A_DO214AB-MFG 2060.2,2170.83 r0 top
D7_3 "SMCJ300A" FP-SMCJ300A_DO214AB-MFG 2820.2,2170.83 r0 top
D7_4 "SMCJ300A" FP-SMCJ300A_DO214AB-MFG 3580.2,2170.83 r0 top
D7_5 "SMCJ300A" FP-SMCJ300A_DO214AB-MFG 4340.19,2170.83 r0 top
D8 "SMCJ300A" FP-SMCJ300A_DO214AB-MFG 370.35,2248.94 r270 bottom
D8_1 "SMCJ300A" FP-SMCJ300A_DO214AB-MFG 1155.35,2248.94 r270 bottom
D8_2 "SMCJ300A" FP-SMCJ300A_DO214AB-MFG 1915.35,2248.94 r270 bottom
D8_3 "SMCJ300A" FP-SMCJ300A_DO214AB-MFG 2675.35,2248.94 r270 bottom
D8_4 "SMCJ300A" FP-SMCJ300A_DO214AB-MFG 3435.35,2248.94 r270 bottom
D8_5 "SMCJ300A" FP-SMCJ300A_DO214AB-MFG 4195.35,2248.94 r270 bottom
D9 "MMSZ5242BS-7-F" SOD-323 489.72,1638.19 r0 top value=12V
D9_1 "MMSZ5242BS-7-F" SOD-323 1249.72,1638.19 r0 top value=12V
D9_2 "MMSZ5242BS-7-F" SOD-323 2009.72,1638.19 r0 top value=12V
D9_3 "MMSZ5242BS-7-F" SOD-323 2769.72,1638.19 r0 top value=12V
D9_4 "MMSZ5242BS-7-F" SOD-323 3529.72,1638.19 r0 top value=12V
D9_5 "MMSZ5242BS-7-F" SOD-323 4289.72,1638.19 r0 top value=12V
D10 "BAT54WS-7-F" SOD-323 718.35,2358.82 r270 top value=30V
D10_1 "BAT54WS-7-F" SOD-323 1476.1,2350 r270 top value=30V
D10_2 "BAT54WS-7-F" SOD-323 2233.35,2345 r270 top value=30V
D10_3 "BAT54WS-7-F" SOD-323 2996.1,2350 r270 top value=30V
D10_4 "BAT54WS-7-F" SOD-323 3755.94,2335 r270 top value=30V
D10_5 "BAT54WS-7-F" SOD-323 4515.94,2345 r270 top value=30V
D13 "150060RS75000" WL-SMCW_RED 5783.35,305 r90 top value=Red
FID1 "Fiducial" Fiducial10-20 6170,1822.54 r0 top
FID2 "Fiducial" Fiducial10-20 6175,110 r0 top
FID3 "Fiducial" Fiducial10-20 85,110 r0 top
FID4 "Fiducial" Fiducial10-20 95,130 r90 bottom
FID5 "Fiducial" Fiducial10-20 6150,2755 r90 bottom
FID6 "Fiducial" Fiducial10-20 6160,110 r90 bottom
"High Voltage1" "DANGER HIGH VOLTAGE" IEC_HighVoltage_Small 175,1305 r90 bottom
"High Voltage2" "DANGER HIGH VOLTAGE" IEC_HighVoltage_Small 160,1285 r90 top
J1 "TSW-110-08-G-T-RA" FP-TSW-110-08-G-T-RA_HDR30-MFG 5683.35,2671.94 r180 top
J2 "PPPC032LFBN-RC" Sullins_xxxC032LFBN-RC 5285,2040 r90 bottom
J3 "SSQ-102-03-G-S" Samtec_SSQ-102-03-x-S 5425.6,655 r90 bottom
J4 "PPPC031LFBN-RC" Sullins_PPPC031LFBN-RC 873.43,2239.72 r270 bottom
J4_1 "PPPC031LFBN-RC" Sullins_PPPC031LFBN-RC 1633.42,2239.73 r270 bottom
J4_2 "PPPC031LFBN-RC" Sullins_PPPC031LFBN-RC 2393.43,2239.72 r270 bottom
J4_3 "PPPC031LFBN-RC" Sullins_PPPC031LFBN-RC 3153.43,2239.72 r270 bottom
J4_4 "PPPC031LFBN-RC" Sullins_PPPC031LFBN-RC 3913.42,2239.72 r270 bottom
J4_5 "PPPC031LFBN-RC" Sullins_PPPC031LFBN-RC 4674.11,2240 r270 bottom
J5 "TSW-105-08-G-S-RA-004" FP-TSW-105-08-G-S-RA-004_HDR4-MFG 727.68,2672.87 r180 top
J5_1 "TSW-105-08-G-S-RA-004" FP-TSW-105-08-G-S-RA-004_HDR4-MFG 1497.67,2672.88 r180 top
J5_2 "TSW-104-08-G-S-RA-003" FP-TSW-104-08-G-S-RA-003_HDR3-MFG 2277.68,2672.87 r180 top
J5_3 "TSW-105-08-G-S-RA-004" FP-TSW-105-08-G-S-RA-004_HDR4-MFG 3027.68,2672.87 r180 top
J5_4 "TSW-104-08-G-S-RA-003" FP-TSW-104-08-G-S-RA-003_HDR3-MFG 3797.68,2672.87 r180 top
J5_5 "TSW-105-08-G-S-RA-004" FP-TSW-105-08-G-S-RA-004_HDR4-MFG 4547.67,2672.88 r180 top
J6 "SSQ-102-03-G-S" Samtec_SSQ-102-03-x-S 204.79,655 r90 bottom
J7 "TSW-102-08-G-S-RA" TSW-102-08-G-S-RA 133.03,2565 r180 top
Logo1 "CE Mark" CE_Mark_5mm 4895.58,267 r90 top
Logo3 "WEEE logo" WEEE_Minimum 5225,233.37 r90 top
PWM_1 "5002" Keystone5002 4138.35,400.16 r90 top
PWM_2 "5002" Keystone5002 3382.24,379.49 r90 top
PWM_3 "5002" Keystone5002 2622.24,379.49 r90 top
PWM_4 "5002" Keystone5002 1862.24,379.49 r90 top
PWM_5 "5002" Keystone5002 1102.23,379.49 r90 top
PWM_6 "5002" Keystone5002 342.24,379.49 r90 top
Q1 "BC856A-7-F" SOT-23 5958.35,302.82 r0 top value="65 V"
Q2 "SI2318CDS-T1-GE3" SOT-23 813.94,1572.4 r180 top value=40V
Q2_1 "SI2318CDS-T1-GE3" SOT-23 1573.93,1572.4 r180 top value=40V
Q2_2 "SI2318CDS-T1-GE3" SOT-23 2333.94,1572.4 r180 top value=40V
Q2_3 "SI2318CDS-T1-GE3" SOT-23 3093.94,1572.4 r180 top value=40V
Q2_4 "SI2318CDS-T1-GE3" SOT-23 3853.94,1572.4 r180 top value=40V
Q2_5 "SI2318CDS-T1-GE3" SOT-23 4613.93,1572.41 r180 top value=40V
Q3 "BC856A-7-F" SOT-23 5668.35,305 r0 top value="65 V"
R1 "ERJ-3EKF2002V" 0603 5958.35,417.82 r180 top value=20.0k
R2 "CRCW060310K0JNEA" 0603 3980,175 r0 bottom value=10k
R3 "CRCW0402120RJNED" 0402 6133.35,302.82 r270 top value=120
R4 "CRCW06031K00FKEA" 0603 381.3,1816.5 r90 bottom value=1.00k
R4_1 "CRCW06031K00FKEA" 0603 1141.3,1816.5 r90 bottom value=1.00k
R4_2 "CRCW06031K00FKEA" 0603 1901.3,1816.5 r90 bottom value=1.00k
R4_3 "CRCW06031K00FKEA" 0603 2661.3,1816.5 r90 bottom value=1.00k
R4_4 "CRCW06031K00FKEA" 0603 3421.3,1816.5 r90 bottom value=1.00k
R4_5 "CRCW06031K00FKEA" 0603 4181.3,1816.5 r90 bottom value=1.00k
R7 "CRCW080510R0FKEA" 0805_HV 483.35,1544.21 r180 top value=10.0
R7_1 "CRCW080510R0FKEA" 0805_HV 1243.34,1544.21 r180 top value=10.0
R7_2 "CRCW080510R0FKEA" 0805_HV 2003.35,1544.21 r180 top value=10.0
R7_3 "CRCW080510R0FKEA" 0805_HV 2763.35,1544.21 r180 top value=10.0
R7_4 "CRCW080510R0FKEA" 0805_HV 3523.35,1544.21 r180 top value=10.0
R7_5 "CRCW080510R0FKEA" 0805_HV 4283.34,1544.22 r180 top value=10.0
R8 "CRCW080510R0JNEA" 0805_HV 567.09,778.11 r0 bottom value=10
R8_1 "CRCW080510R0JNEA" 0805_HV 1327.08,778.11 r0 bottom value=10
R8_2 "CRCW080510R0JNEA" 0805_HV 2063.35,760 r0 bottom value=10
R8_3 "CRCW080510R0JNEA" 0805_HV 2823.35,760 r0 bottom value=10
R8_4 "CRCW080510R0JNEA" 0805_HV 3588.35,760 r0 bottom value=10
R8_5 "CRCW080510R0JNEA" 0805_HV 4341.93,760 r0 bottom value=10
R9 "ERJ-3EKF1002V" 0603 711.63,635.4 r180 top value=10.0k
R9_1 "ERJ-3EKF1002V" 0603 1466.26,635.4 r180 top value=10.0k
R9_2 "ERJ-3EKF1002V" 0603 2226.26,635.39 r180 top value=10.0k
R9_3 "ERJ-3EKF1002V" 0603 2986.26,635.39 r180 top value=10.0k
R9_4 "ERJ-3EKF1002V" 0603 3746.26,635.39 r180 top value=10.0k
R9_5 "ERJ-3EKF1002V" 0603 4506.26,635.4 r180 top value=10.0k
R10 "ERJ-3EKF1002V" 0603 719.06,448.39 r180 top value=10.0k
R10_1 "ERJ-3EKF1002V" 0603 1479.05,448.39 r180 top value=10.0k
R10_2 "ERJ-3EKF1002V" 0603 2239.05,448.39 r180 top value=10.0k
R10_3 "ERJ-3EKF1002V" 0603 2999.05,448.39 r180 top value=10.0k
R10_4 "ERJ-3EKF1002V" 0603 3759.05,448.39 r180 top value=10.0k
R10_5 "ERJ-3EKF1002V" 0603 4519.05,448.39 r180 top value=10.0k
R11 "ERJ-3EKF1002V" 0603 496.61,340.12 r0 top value=10.0k
R11_1 "ERJ-3EKF1002V" 0603 1256.61,340.12 r0 top value=10.0k
R11_2 "ERJ-3EKF1002V" 0603 2018.35,340.12 r0 top value=10.0k
R11_3 "ERJ-3EKF1002V" 0603 2776.61,340.12 r0 top value=10.0k
R11_4 "ERJ-3EKF1002V" 0603 3576.61,340.24 r0 top value=10.0k
R11_5 "ERJ-3EKF1002V" 0603 4339.41,337.17 r0 top value=10.0k
R12 "CRCW060310K0JNEA" 0603 583.63,2485 r0 top value=10k
R12_1 "CRCW060310K0JNEA" 0603 1363.35,2485 r0 top value=10k
R12_2 "CRCW060310K0JNEA" 0603 2188.53,2495 r0 top value=10k
R12_3 "CRCW060310K0JNEA" 0603 2883.35,2490 r0 top value=10k
R12_4 "CRCW060310K0JNEA" 0603 3703.35,2495 r0 top value=10k
R12_5 "CRCW060310K0JNEA" 0603 4405.94,2490 r0 top value=10k
R13 "CRCW0603100RJNEA" 0603 496.61,596.02 r0 top value=100
R13_1 "CRCW0603100RJNEA" 0603 1256.61,596.03 r0 top value=100
R13_2 "CRCW0603100RJNEA" 0603 2016.61,596.02 r0 top value=100
R13_3 "CRCW0603100RJNEA" 0603 2776.61,596.02 r0 top value=100
R13_4 "CRCW0603100RJNEA" 0603 3536.61,596.02 r0 top value=100
R13_5 "CRCW0603100RJNEA" 0603 4296.61,596.03 r0 top value=100
R14 "CRCW0603100RJNEA" 0603 496.61,409.02 r0 top value=100
R14_1 "CRCW0603100RJNEA" 0603 1256.61,409.02 r0 top value=100
R14_2 "CRCW0603100RJNEA" 0603 2016.61,409.02 r0 top value=100
R14_3 "CRCW0603100RJNEA" 0603 2776.61,409.02 r0 top value=100
R14_4 "CRCW0603100RJNEA" 0603 3536.61,409.02 r0 top value=100
R14_5 "CRCW0603100RJNEA" 0603 4296.61,409.02 r0 top value=100
R15 "CRCW08050000Z0EA" 0805_HV 639.33,1560.59 r270 top value=0
R15_1 "CRCW08050000Z0EA" 0805_HV 1399.33,1560.59 r270 top value=0
R15_2 "CRCW08050000Z0EA" 0805_HV 2159.33,1560.59 r270 top value=0
R15_3 "CRCW08050000Z0EA" 0805_HV 2919.33,1560.59 r270 top value=0
R15_4 "CRCW08050000Z0EA" 0805_HV 3679.33,1560.59 r270 top value=0
R15_5 "CRCW08050000Z0EA" 0805_HV 4439.33,1560.6 r270 top value=0
R16 "CRCW08050000Z0EA" 0805_HV 808.62,1452.32 r180 top value=0
R16_1 "CRCW08050000Z0EA" 0805_HV 1568.62,1452.32 r180 top value=0
R16_2 "CRCW08050000Z0EA" 0805_HV 2328.62,1452.32 r180 top value=0
R16_3 "CRCW08050000Z0EA" 0805_HV 3088.62,1452.32 r180 top value=0
R16_4 "CRCW08050000Z0EA" 0805_HV 3848.62,1452.32 r180 top value=0
R16_5 "CRCW08050000Z0EA" 0805_HV 4608.62,1452.33 r180 top value=0
R17 "CRCW0603100RJNEA" 0603 735.79,419.84 r90 bottom value=100
R17_1 "CRCW0603100RJNEA" 0603 1495.78,419.84 r90 bottom value=100
R17_2 "CRCW0603100RJNEA" 0603 2255.79,419.84 r90 bottom value=100
R17_3 "CRCW0603100RJNEA" 0603 3015.79,419.84 r90 bottom value=100
R17_4 "CRCW0603100RJNEA" 0603 3775.79,419.84 r90 bottom value=100
R17_5 "CRCW0603100RJNEA" 0603 4554.26,414.69 r90 bottom value=100
R18 "CRCW06031K00FKEA" 0603 365.39,1763.58 r90 top value=1.00k
R18_1 "CRCW06031K00FKEA" 0603 1125.39,1763.58 r90 top value=1.00k
R18_2 "CRCW06031K00FKEA" 0603 1885.39,1763.58 r90 top value=1.00k
R18_3 "CRCW06031K00FKEA" 0603 2645.39,1763.58 r90 top value=1.00k
R18_4 "CRCW06031K00FKEA" 0603 3405.39,1763.58 r90 top value=1.00k
R18_5 "CRCW06031K00FKEA" 0603 4165.39,1763.59 r90 top value=1.00k
R19 "CRCW0603100RJNEA" 0603 676.73,418.86 r90 bottom value=100
R19_1 "CRCW0603100RJNEA" 0603 1436.73,418.86 r90 bottom value=100
R19_2 "CRCW0603100RJNEA" 0603 2196.73,418.86 r90 bottom value=100
R19_3 "CRCW0603100RJNEA" 0603 2956.73,418.86 r90 bottom value=100
R19_4 "CRCW0603100RJNEA" 0603 3716.73,418.86 r90 bottom value=100
R19_5 "CRCW0603100RJNEA" 0603 4493.35,434.52 r90 bottom value=100
R20 "RCG060310K0FKEA" 0603 794.69,1674.09 r180 top value=10.0k
R20_1 "RCG060310K0FKEA" 0603 1554.68,1674.1 r180 top value=10.0k
R20_2 "RCG060310K0FKEA" 0603 2314.68,1674.09 r180 top value=10.0k
R20_3 "RCG060310K0FKEA" 0603 3074.69,1674.09 r180 top value=10.0k
R20_4 "RCG060310K0FKEA" 0603 3834.68,1674.09 r180 top value=10.0k
R20_5 "RCG060310K0FKEA" 0603 4594.68,1674.1 r180 top value=10.0k
R21 "CRCW06031K00FKEA" 0603 430.51,1934.61 r270 top value=1.00k
R21_1 "CRCW06031K00FKEA" 0603 1190.51,1934.61 r270 top value=1.00k
R21_2 "CRCW06031K00FKEA" 0603 1950.51,1934.61 r270 top value=1.00k
R21_3 "CRCW06031K00FKEA" 0603 2710.51,1934.61 r270 top value=1.00k
R21_4 "CRCW06031K00FKEA" 0603 3470.51,1934.61 r270 top value=1.00k
R21_5 "CRCW06031K00FKEA" 0603 4230.51,1934.61 r270 top value=1.00k
R22 "CRCW06030000Z0EA" 0603 365.39,1891.54 r90 top value=0
R22_1 "CRCW06030000Z0EA" 0603 1125.39,1891.54 r90 top value=0
R22_2 "CRCW06030000Z0EA" 0603 1885.39,1891.53 r90 top value=0
R22_3 "CRCW06030000Z0EA" 0603 2645.39,1891.54 r90 top value=0
R22_4 "CRCW06030000Z0EA" 0603 3405.39,1891.53 r90 top value=0
R22_5 "CRCW06030000Z0EA" 0603 4165.39,1891.54 r90 top value=0
R23 "CRCW201010R0JNEF" 2010 711.63,1885.39 r90 top value=10
R23_1 "CRCW201010R0JNEF" 2010 1471.63,1885.4 r90 top value=10
R23_2 "CRCW201010R0JNEF" 2010 2231.63,1885.39 r90 top value=10
R23_3 "CRCW201010R0JNEF" 2010 2991.63,1885.39 r90 top value=10
R23_4 "CRCW201010R0JNEF" 2010 3751.63,1885.39 r90 top value=10
R23_5 "CRCW201010R0JNEF" 2010 4511.63,1885.4 r90 top value=10
R24 "CRCW201010R0JNEF" 2010 848.62,1885.39 r90 top value=10
R24_1 "CRCW201010R0JNEF" 2010 1608.62,1885.4 r90 top value=10
R24_2 "CRCW201010R0JNEF" 2010 2368.62,1885.39 r90 top value=10
R24_3 "CRCW201010R0JNEF" 2010 3128.62,1885.39 r90 top value=10
R24_4 "CRCW201010R0JNEF" 2010 3888.62,1885.39 r90 top value=10
R24_5 "CRCW201010R0JNEF" 2010 4648.62,1885.4 r90 top value=10
R25 "CRCW06030000Z0EA" 0603 430.51,1805.67 r270 top value=0
R25_1 "CRCW06030000Z0EA" 0603 1190.51,1805.67 r270 top value=0
R25_2 "CRCW06030000Z0EA" 0603 1950.51,1805.67 r270 top value=0
R25_3 "CRCW06030000Z0EA" 0603 2710.51,1805.67 r270 top value=0
R25_4 "CRCW06030000Z0EA" 0603 3470.51,1805.67 r270 top value=0
R25_5 "CRCW06030000Z0EA" 0603 4230.51,1805.67 r270 top value=0
R26 "CRCW201010R0JNEF" 2010 699.06,1884.25 r90 bottom value=10
R26_1 "CRCW201010R0JNEF" 2010 1459.05,1884.25 r90 bottom value=10
R26_2 "CRCW201010R0JNEF" 2010 2219.05,1884.25 r90 bottom value=10
R26_3 "CRCW201010R0JNEF" 2010 2979.06,1884.25 r90 bottom value=10
R26_4 "CRCW201010R0JNEF" 2010 3739.05,1884.25 r90 bottom value=10
R26_5 "CRCW201010R0JNEF" 2010 4499.05,1884.26 r90 bottom value=10
R27 "RC0603FR-07620RL" 0603 5975,2015 r180 bottom value=620
R28 "CRCW201010R0JNEF" 2010 842.09,1884.25 r90 bottom value=10
R28_1 "CRCW201010R0JNEF" 2010 1602.08,1884.25 r90 bottom value=10
R28_2 "CRCW201010R0JNEF" 2010 2362.09,1884.25 r90 bottom value=10
R28_3 "CRCW201010R0JNEF" 2010 3122.09,1884.25 r90 bottom value=10
R28_4 "CRCW201010R0JNEF" 2010 3882.09,1884.25 r90 bottom value=10
R28_5 "CRCW201010R0JNEF" 2010 4642.08,1884.26 r90 bottom value=10
R29 "ERJ-3EKF2002V" 0603 5663.35,410 r180 top value=20.0k
R30 "CRCW0402120RJNED" 0402 5843.35,305 r270 top value=120
U1 "UCC5870-DWJ" DWJ0036A 637.36,970.04 r90 top
U1_1 "UCC5870-DWJ" DWJ0036A 1397.36,970.04 r90 top
U1_2 "UCC5870-DWJ" DWJ0036A 2157.36,970.04 r90 top
U1_3 "UCC5870-DWJ" DWJ0036A 2917.36,970.04 r90 top
U1_4 "UCC5870-DWJ" DWJ0036A 3677.36,970.04 r90 top
U1_5 "UCC5870-DWJ" DWJ0036A 4437.36,970.04 r90 top
ZZ1 "This Assembly Note is for PCB labels only" AssemblyNoteLabel 204.69,5197.84 r0 top
ZZ2 "These assemblies are ESD sensitive, ESD precautions shall be observed." AssemblyNote 204.69,5088.96 r0 top
ZZ3 "These assemblies must be clean and free from flux and all contaminants. Use of no clean flux is not acceptable." AssemblyNote 204.69,5000.4 r0 top
ZZ4 "These assemblies must comply with workmanship standards IPC-A-610 Class 2, unless otherwise specified." AssemblyNote 204.69,4911.84 r0 top

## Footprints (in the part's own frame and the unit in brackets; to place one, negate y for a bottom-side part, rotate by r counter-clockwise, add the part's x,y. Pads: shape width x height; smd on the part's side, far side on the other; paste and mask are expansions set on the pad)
0402 [mm] "0402 from SM-752 data"
  rect 0.8x0.6 smd: 1(-0.6,0) 2(0.6,0)
  silkscreen extent -1.22,-0.52 1.22,0.52, body extent -0.55,-0.3 0.55,0.3, height 0.6
0603 [mm] "0603 from SM-752 data"
  rect 1x0.95 smd: 1(-0.8,0) 2(0.8,0)
  silkscreen extent -1.52,-0.69 1.52,0.69, body extent -0.87,-0.47 0.87,0.47, height 1
0805_HV [mil] "0805 with 30mil clearance between pads"
  rect 50x63 smd: 1(-40,0) 2(40,0)
  silkscreen extent -74,-40 74,40, body extent -43,-29 43,29, height 57
1206_180 [mm] "1206_180"
  rect 1.1x1.6 smd: 1(-1.7,0) 2(1.7,0)
  silkscreen extent -0.9,-1 0.9,1, body extent -1.75,-0.95 1.75,0.95, height 1.8
2010 [mm] "Chip Capacitor, Body 5.08x2.54mm, IPC Medium Density"
  rect 1.6x2.7 smd: 1(-2.3,0) 2(2.3,0)
  silkscreen extent -3.42,-1.65 3.42,1.65, body extent -2.73,-1.45 2.73,1.45, height 1.66
AssemblyNote [mil] "Assembly Note"
AssemblyNoteLabel [mil] "Assembly Note for PCB Labels"
CE_Mark_5mm [mil] "Minimum text height for CE Mark"
  silkscreen extent -138,-98 138,98
DWJ0036A [mm] "SOP, 36-Leads, Body 12.8x7.5mm, Pitch 0.65mm"
  rrect22% 1.85x0.45 smd: 1(-4.975,5.525) 2(-4.975,4.875) 3(-4.975,4.225) 4(-4.975,3.575) 5(-4.975,2.925) 6(-4.975,2.275) 7(-4.975,1.625) 8(-4.975,0.975) 9(-4.975,0.325) 10(-4.975,-0.325) 11(-4.975,-0.975) 12(-4.975,-1.625) 13(-4.975,-2.275) 14(-4.975,-2.925) 15(-4.975,-3.575) 16(-4.975,-4.225) 17(-4.975,-4.875) 18(-4.975,-5.525) 19(4.975,-5.525) 20(4.975,-4.875) 21(4.975,-4.225) 22(4.975,-3.575) 23(4.975,-2.925) 24(4.975,-2.275) 25(4.975,-1.625) 26(4.975,-0.975) 27(4.975,-0.325) 28(4.975,0.325) 29(4.975,0.975) 30(4.975,1.625) 31(4.975,2.275) 32(4.975,2.925) 33(4.975,3.575) 34(4.975,4.225) 35(4.975,4.875) 36(4.975,5.525)
  body extent -5.15,-6.41 5.15,6.42, height 3.38
Fiducial10-20 [mm]
  round 1 smd mask+0.5: 1(0,0)
  Top Layer keep-out circle w1.178: c0,0 r0.5
FP-SMCJ300A_DO214AB-MFG [mm]
  rrect4% 2.4x3.3 smd paste+0 mask+0: 1(-3.3,0) 2(3.3,0)
  silkscreen extent -5.27,-3.11 3.55,3.11, body extent -4.6,-3.21 4.6,3.21, height 0.25
FP-TSW-104-08-G-S-RA-003_HDR3-MFG [mm]
  rrect6% 1.57x1.57 hole 1.02 paste-1000 mask+0: 1(3.81,2.77)
  round 1.57 hole 1.02 paste-1000 mask+0: 2(1.27,2.77) 4(-3.81,2.77)
  silkscreen extent -5.27,-1.34 5.27,4.25, body extent -5.37,-7.4 5.37,3.65, height 0.25
FP-TSW-105-08-G-S-RA-004_HDR4-MFG [mm]
  rrect6% 1.57x1.57 hole 1.02 paste-1000 mask+0: 1(5.08,2.77)
  round 1.57 hole 1.02 paste-1000 mask+0: 2(2.54,2.77) 3(0,2.77) 5(-5.08,2.77)
  silkscreen extent -6.5,-1.34 6.5,4.27, body extent -6.6,-7.4 6.6,3.65, height 0.25
FP-TSW-110-08-G-T-RA_HDR30-MFG [mm]
  rrect6% 1.57x1.57 hole 1.02 paste-1000 mask+0: 1(-11.43,2.77)
  round 1.57 hole 1.02 paste-1000 mask+0: 2(-11.43,5.31) 3(-11.43,7.85) 4(-8.89,2.77) 5(-8.89,5.31) 6(-8.89,7.85) 7(-6.35,2.77) 8(-6.35,5.31) 9(-6.35,7.85) 10(-3.81,2.77) 11(-3.81,5.31) 12(-3.81,7.85) 13(-1.27,2.77) 14(-1.27,5.31) 15(-1.27,7.85) 16(1.27,2.77) 17(1.27,5.31) 18(1.27,7.85) 19(3.81,2.77) 20(3.81,5.31) 21(3.81,7.85) 22(6.35,2.77) 23(6.35,5.31) 24(6.35,7.85) 25(8.89,2.77) 26(8.89,5.31) 27(8.89,7.85) 28(11.43,2.77) 29(11.43,5.31) 30(11.43,7.85)
  silkscreen extent -13.8,-1.4 12.83,2.89, body extent -12.93,-7.47 12.93,8.73, height 0.25
IEC_HighVoltage_Small [mil]
  silkscreen extent -107,-88 107,97
Keystone5002 [mil] "For Keystone 500x miniature loop terminals"
  round 80 hole 40: 1(0,0)
  silkscreen extent -52,-52 52,52, body extent -49,-49 49,49, height 182
Samtec_SSQ-102-03-x-S [mm] "Receptacle, 2.54mm, 2x1, TH"
  rect 1.55x1.55 hole 1.02: 1(-1.27,0)
  round 1.55 hole 1.02: 2(1.27,0)
  silkscreen extent -2.9,-1.3 2.9,1.3, body extent -2.79,-1.21 2.79,1.21, height 8.51
SMA [mm] "Molded Diode, 2-Leads, Body 4.3x2.6mm, IPC Medium Density, based on OnSemi component dimensions and land pattern"
  rect 2x2 smd: 1(-2,0) 2(2,0)
  silkscreen extent -3.66,-1.57 2.79,1.57, body extent -2.6,-1.3 2.6,1.3, height 2.42
SOD-323 [mm] "NXP recommended land pattern"
  rect 0.6x0.6 smd paste-0.05: 1(-1.1,0) 2(1.1,0)
  silkscreen extent -2.06,-0.86 1.53,0.86, body extent -1.3,-0.67 1.3,0.68, height 1.1
SOT-23 [mm] "SOT23, 3-Leads, Body 2.9x1.3mm, Pitch 0.95mm, Lead Span 2.5mm, IPC Medium Density"
  rrect50% 1x0.6 smd: 1(-1.2,0.95) 2(-1.2,-0.95) 3(1.2,0)
  silkscreen extent -1.63,-1.5 0.7,1.5, body extent -1.16,-1.45 1.21,1.45, height 1
Sullins_PPPC031LFBN-RC [mm] "Sullins"
  rect 1.6x1.6 hole 1.016: 1(-2.54,0)
  round 1.6 hole 1.016: 2(0,0) 3(2.54,0)
  silkscreen extent -4.16,-1.37 4.16,1.9, body extent -4.16,-1.37 4.16,1.37, height 8.71
Sullins_xxxC032LFBN-RC [mm] "Receptacle, 2.54mm, 3x2, TH"
  rrect50% 1.53x1.53 hole 1.02: 1(-2.54,1.27)
  round 1.53 hole 1.02: 2(-2.54,-1.27) 3(0,1.27) 4(0,-1.27) 5(2.54,1.27) 6(2.54,-1.27)
  body extent -4.06,-2.54 4.06,2.54, height 8.5
TSW-102-08-G-S-RA [mm] "Samtec Right Angle Header"
  rrect6% 1.65x1.65 hole 1: 1(-1.27,0)
  round 1.65 hole 1: 2(1.27,0)
  silkscreen extent -2.77,-4.06 2.54,0.11, body extent -2.54,-9.91 2.54,0.32, height 3.05
WEEE_Minimum [mil] "WEEElie bin"
  silkscreen extent -95,-172 99,104
WL-SMCW_GREEN [mm] "WURTH"
  rect 0.8x0.8 smd: 1(-0.8,0) 2(0.8,0)
  silkscreen extent -1.9,-0.8 1.2,0.8, body extent -0.85,-0.45 0.85,0.45, height 0.8
WL-SMCW_RED [mm] "WURTH"
  rect 0.8x0.8 smd: 1(-0.8,0) 2(0.8,0)
  silkscreen extent -1.9,-0.8 1.2,0.8, body extent -0.85,-0.45 0.85,0.45, height 0.8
